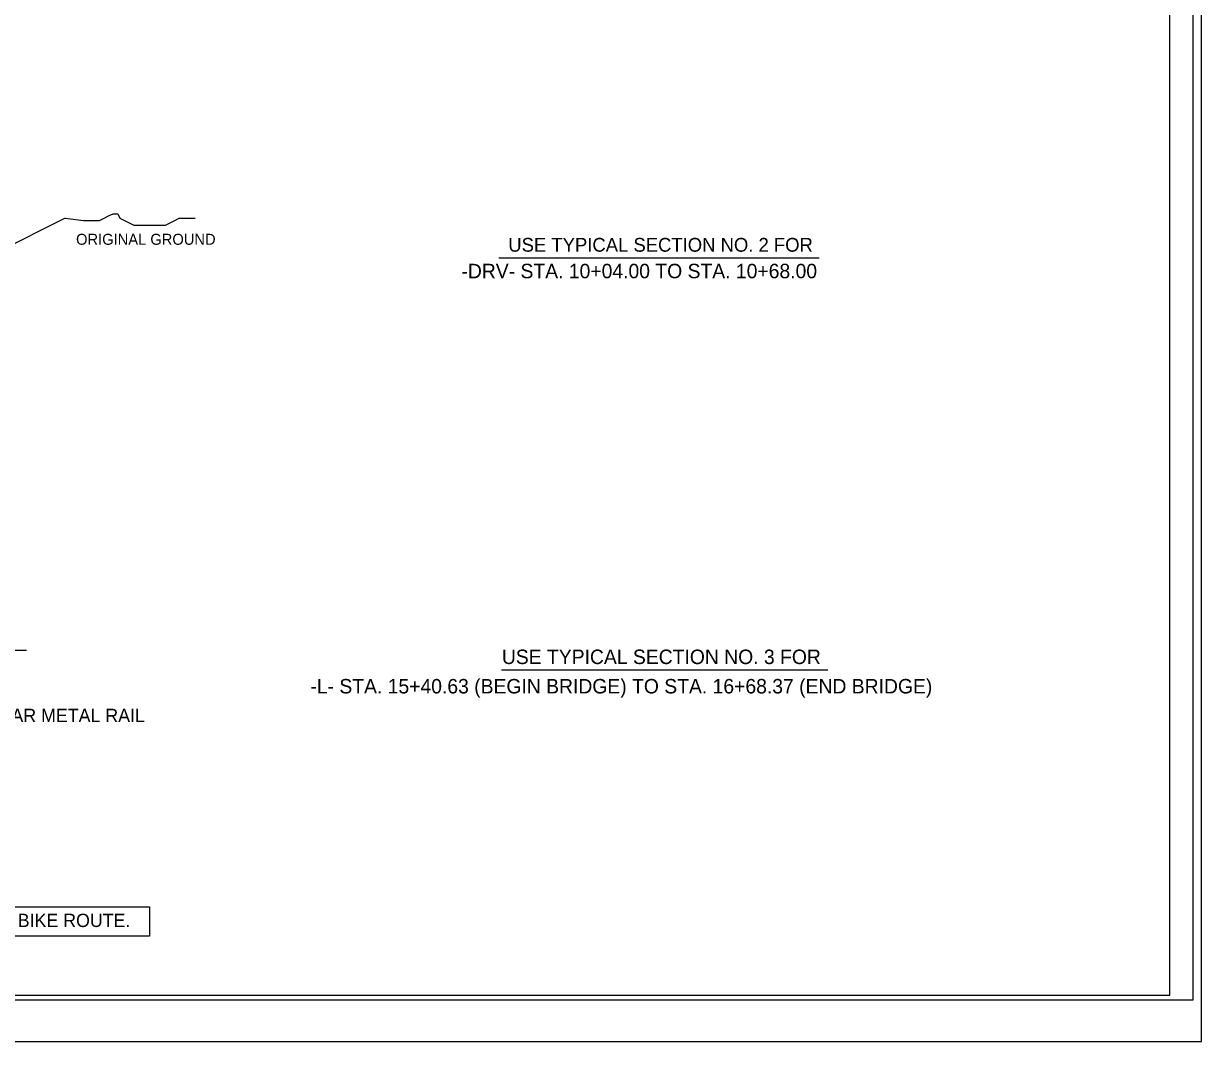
# Model space of a CAD drawing. Extents: x 693533 to 693723, y 486383 to 486493.
# Drawn here: x 693637.4 to 693701.1, y 486383.3 to 486438.3 of the extents above; entities that cross this region are included whole.
import ezdxf

# ---------------------------------------------------------------- set-up
doc = ezdxf.new("R2010")
doc.units = 0
for name, color, linetype in [('Old_Level_1', 7, 'Continuous'), ('Old_Level_11', 7, 'Continuous'), ('Old_Level_28', 7, 'Continuous'), ('Sheet Cutting Line CELL', 7, 'Continuous'), ('Sheet Plot Border Inside CELL', 7, 'Continuous'), ('Sheet Plot Border Outside CELL', 7, 'Continuous'), ('Sheet Typical CELL', 7, 'Continuous'), ('Typical Hinge Slope Arterial CELL', 7, 'Continuous'), ('Typical Shoulder Slope CELL', 7, 'Continuous'), ('Typical Text Label CELL', 7, 'Continuous')]:
    doc.layers.add(name, color=color, linetype=linetype)

msp = doc.modelspace()

# ---------------------------------------------------------------- linework, layer by layer
at = {"layer": 'Old_Level_1'}
msp.add_lwpolyline([(693595.018, 486390.588), (693644.204, 486390.588), (693644.204, 486388.993), (693595.018, 486388.993)], close=True, dxfattribs=at)
at = {"layer": 'Old_Level_11'}
msp.add_line((693663.233, 486403.4), (693680.859, 486403.4), dxfattribs=at)
at = {"layer": 'Old_Level_28'}
msp.add_line((693634.581, 486404.454), (693637.549, 486404.454), dxfattribs=at)
at = {"layer": 'Sheet Cutting Line CELL'}
msp.add_line((693532.659, 486383.314), (693701.059, 486383.314), dxfattribs=at)
at = {"layer": 'Sheet Plot Border Inside CELL'}
msp.add_lwpolyline([(693700.609, 486491.069), (693533.959, 486491.069), (693533.959, 486385.559), (693700.609, 486385.559)], close=True, dxfattribs=at)
at = {"layer": 'Sheet Plot Border Outside CELL'}
msp.add_lwpolyline([(693701.059, 486493.314), (693532.659, 486493.314), (693532.659, 486383.314), (693701.059, 486383.314)], close=True, dxfattribs=at)
at = {"layer": 'Sheet Typical CELL'}
msp.add_lwpolyline([(693699.359, 486490.814), (693549.359, 486490.814), (693549.359, 486385.814), (693699.359, 486385.814)], close=True, dxfattribs=at)
at = {"layer": 'Typical Hinge Slope Arterial CELL'}
msp.add_lwpolyline([(693639.65, 486427.792), (693640.636, 486427.669), (693640.882, 486427.669), (693641.252, 486427.669), (693641.498, 486427.669), (693641.745, 486427.792), (693641.991, 486427.916), (693642.237, 486428.039), (693642.484, 486428.039), (693642.607, 486427.792), (693642.854, 486427.669), (693643.1, 486427.546), (693643.347, 486427.423), (693643.593, 486427.423), (693643.839, 486427.423), (693644.086, 486427.423), (693644.332, 486427.423), (693644.578, 486427.423), (693644.825, 486427.423), (693645.071, 486427.423), (693645.317, 486427.546), (693645.564, 486427.669), (693645.81, 486427.792), (693646.18, 486427.792), (693646.427, 486427.792), (693646.673, 486427.792)], dxfattribs=at)
at = {"layer": 'Typical Shoulder Slope CELL'}
msp.add_line((693639.65, 486427.792), (693631.25, 486423.592), dxfattribs=at)
at = {"layer": 'Typical Text Label CELL'}
msp.add_line((693663.083, 486425.648), (693680.406, 486425.648), dxfattribs=at)

# ---------------------------------------------------------------- texts
at = {"layer": 'Old_Level_11'}
msp.add_text('USE TYPICAL SECTION NO. 3 FOR', height=0.78125, dxfattribs=at).set_placement((693663.248, 486403.705))
at = {"layer": 'Old_Level_28'}
for s, p in [('2-BAR METAL RAIL', (693635.246, 486400.57)), ('NOTE: TOWN OF KNIGHTDALE HAS SR 2507 (TURNIPSEED ROAD) DESIGNATED A LOCAL BIKE ROUTE.', (693595.424, 486389.496))]:
    msp.add_text(s, height=0.71875, rotation=360, dxfattribs=at).set_placement(p)
at = {"layer": 'Typical Hinge Slope Arterial CELL'}
msp.add_text('ORIGINAL GROUND', height=0.59365, dxfattribs=at).set_placement((693640.233, 486426.36))
at = {"layer": 'Typical Text Label CELL'}
for s, height, p in [('USE TYPICAL SECTION NO. 2 FOR', 0.74597, (693663.595, 486425.986)), ('-DRV- STA. 10+04.00 TO STA. 10+68.00', 0.78125, (693661.063, 486424.551)), ('-L- STA. 15+40.63 (BEGIN BRIDGE) TO STA. 16+68.37 (END BRIDGE)', 0.78125, (693652.896, 486402.117))]:
    msp.add_text(s, height=height, dxfattribs=at).set_placement(p)

doc.saveas('drawing.dxf')
